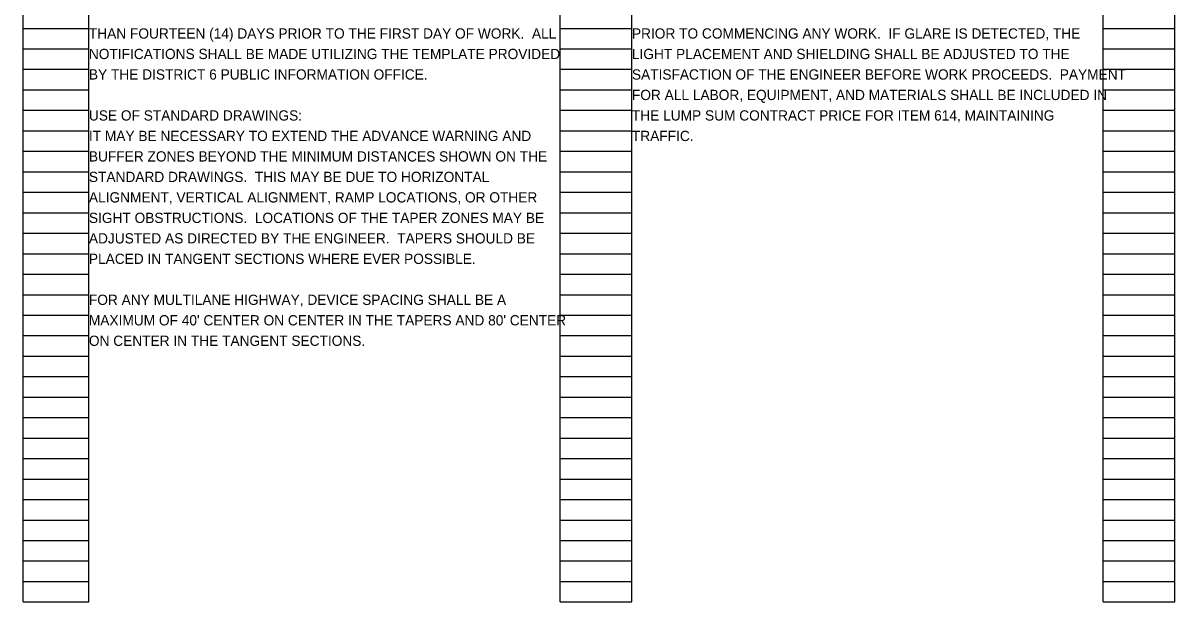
# Model space of a CAD drawing. Extents: x 0 to 32, y -44 to 21.1.
# Drawn here: x 1.5 to 17.24, y 0.98 to 8.89 of the extents above; entities that cross this region are included whole.
import ezdxf

# ---------------------------------------------------------------- set-up
doc = ezdxf.new("R2010")
doc.units = 0
doc.layers.add('SH_Data', color=7, linetype='Continuous')
doc.layers.add('SH_Text', color=7, linetype='Continuous')

msp = doc.modelspace()

# ---------------------------------------------------------------- linework, layer by layer
at = {"layer": 'SH_Data'}
for p, q in [((1.5, 0.98), (1.5, 21.14)), ((2.4, 0.98), (2.4, 21.14)), ((8.84, 0.98), (8.84, 21.14)), ((9.82, 0.98), (9.82, 21.14)), ((16.26, 0.98), (16.26, 21.14)), ((17.24, 0.98), (17.24, 21.14)), ((1.5, 8.82), (2.4, 8.82)), ((8.84, 8.82), (9.82, 8.82)), ((16.26, 8.82), (17.24, 8.82)), ((1.5, 8.54), (2.4, 8.54)), ((8.84, 8.54), (9.82, 8.54)), ((16.26, 8.54), (17.24, 8.54)), ((1.5, 8.26), (2.4, 8.26)), ((8.84, 8.26), (9.82, 8.26)), ((16.26, 8.26), (17.24, 8.26)), ((1.5, 7.98), (2.4, 7.98)), ((8.84, 7.98), (9.82, 7.98)), ((16.26, 7.98), (17.24, 7.98)), ((1.5, 7.7), (2.4, 7.7)), ((8.84, 7.7), (9.82, 7.7)), ((16.26, 7.7), (17.24, 7.7)), ((1.5, 7.42), (2.4, 7.42)), ((8.84, 7.42), (9.82, 7.42)), ((16.26, 7.42), (17.24, 7.42)), ((1.5, 7.14), (2.4, 7.14)), ((8.84, 7.14), (9.82, 7.14)), ((16.26, 7.14), (17.24, 7.14)), ((1.5, 6.86), (2.4, 6.86)), ((8.84, 6.86), (9.82, 6.86)), ((16.26, 6.86), (17.24, 6.86)), ((1.5, 6.58), (2.4, 6.58)), ((8.84, 6.58), (9.82, 6.58)), ((16.26, 6.58), (17.24, 6.58)), ((1.5, 6.3), (2.4, 6.3)), ((8.84, 6.3), (9.82, 6.3)), ((16.26, 6.3), (17.24, 6.3)), ((1.5, 6.02), (2.4, 6.02)), ((8.84, 6.02), (9.82, 6.02)), ((16.26, 6.02), (17.24, 6.02)), ((1.5, 5.74), (2.4, 5.74)), ((8.84, 5.74), (9.82, 5.74)), ((16.26, 5.74), (17.24, 5.74)), ((1.5, 5.46), (2.4, 5.46)), ((8.84, 5.46), (9.82, 5.46)), ((16.26, 5.46), (17.24, 5.46)), ((1.5, 5.18), (2.4, 5.18)), ((8.84, 5.18), (9.82, 5.18)), ((16.26, 5.18), (17.24, 5.18)), ((1.5, 4.9), (2.4, 4.9)), ((8.84, 4.9), (9.82, 4.9)), ((16.26, 4.9), (17.24, 4.9)), ((1.5, 4.62), (2.4, 4.62)), ((8.84, 4.62), (9.82, 4.62)), ((16.26, 4.62), (17.24, 4.62)), ((1.5, 4.34), (2.4, 4.34)), ((8.84, 4.34), (9.82, 4.34)), ((16.26, 4.34), (17.24, 4.34)), ((1.5, 4.06), (2.4, 4.06)), ((8.84, 4.06), (9.82, 4.06)), ((16.26, 4.06), (17.24, 4.06)), ((1.5, 3.78), (2.4, 3.78)), ((8.84, 3.78), (9.82, 3.78)), ((16.26, 3.78), (17.24, 3.78)), ((1.5, 3.5), (2.4, 3.5)), ((8.84, 3.5), (9.82, 3.5)), ((16.26, 3.5), (17.24, 3.5)), ((1.5, 3.22), (2.4, 3.22)), ((8.84, 3.22), (9.82, 3.22)), ((16.26, 3.22), (17.24, 3.22)), ((1.5, 2.94), (2.4, 2.94)), ((8.84, 2.94), (9.82, 2.94)), ((16.26, 2.94), (17.24, 2.94)), ((1.5, 2.66), (2.4, 2.66)), ((8.84, 2.66), (9.82, 2.66)), ((16.26, 2.66), (17.24, 2.66)), ((1.5, 2.38), (2.4, 2.38)), ((8.84, 2.38), (9.82, 2.38)), ((16.26, 2.38), (17.24, 2.38)), ((1.5, 2.1), (2.4, 2.1)), ((8.84, 2.1), (9.82, 2.1)), ((16.26, 2.1), (17.24, 2.1)), ((1.5, 1.82), (2.4, 1.82)), ((8.84, 1.82), (9.82, 1.82)), ((16.26, 1.82), (17.24, 1.82)), ((1.5, 1.54), (2.4, 1.54)), ((8.84, 1.54), (9.82, 1.54)), ((16.26, 1.54), (17.24, 1.54)), ((1.5, 1.26), (2.4, 1.26)), ((8.84, 1.26), (9.82, 1.26)), ((16.26, 1.26), (17.24, 1.26)), ((1.5, 0.98), (2.4, 0.98)), ((8.84, 0.98), (9.82, 0.98)), ((16.26, 0.98), (17.24, 0.98))]:
    msp.add_line(p, q, dxfattribs=at)

# ---------------------------------------------------------------- texts
at = {"layer": 'SH_Text'}
for s, p in [('THAN FOURTEEN (14) DAYS PRIOR TO THE FIRST DAY OF WORK.  ALL ', (2.4, 8.68)), ('PRIOR TO COMMENCING ANY WORK.  IF GLARE IS DETECTED, THE ', (9.82, 8.68)), ('NOTIFICATIONS SHALL BE MADE UTILIZING THE TEMPLATE PROVIDED ', (2.4, 8.4)), ('LIGHT PLACEMENT AND SHIELDING SHALL BE ADJUSTED TO THE ', (9.82, 8.4)), ('BY THE DISTRICT 6 PUBLIC INFORMATION OFFICE.', (2.4, 8.12)), ('SATISFACTION OF THE ENGINEER BEFORE WORK PROCEEDS.  PAYMENT ', (9.82, 8.12)), ('FOR ALL LABOR, EQUIPMENT, AND MATERIALS SHALL BE INCLUDED IN ', (9.82, 7.84)), ('USE OF STANDARD DRAWINGS:', (2.4, 7.56)), ('THE LUMP SUM CONTRACT PRICE FOR ITEM 614, MAINTAINING ', (9.82, 7.56)), ('IT MAY BE NECESSARY TO EXTEND THE ADVANCE WARNING AND ', (2.4, 7.28)), ('TRAFFIC.', (9.82, 7.28)), ('BUFFER ZONES BEYOND THE MINIMUM DISTANCES SHOWN ON THE ', (2.4, 7)), ('STANDARD DRAWINGS.  THIS MAY BE DUE TO HORIZONTAL ', (2.4, 6.72)), ('ALIGNMENT, VERTICAL ALIGNMENT, RAMP LOCATIONS, OR OTHER ', (2.4, 6.44)), ('SIGHT OBSTRUCTIONS.  LOCATIONS OF THE TAPER ZONES MAY BE ', (2.4, 6.16)), ('ADJUSTED AS DIRECTED BY THE ENGINEER.  TAPERS SHOULD BE ', (2.4, 5.88)), ('PLACED IN TANGENT SECTIONS WHERE EVER POSSIBLE.  ', (2.4, 5.6)), ('FOR ANY MULTILANE HIGHWAY, DEVICE SPACING SHALL BE A ', (2.4, 5.04)), ("MAXIMUM OF 40' CENTER ON CENTER IN THE TAPERS AND 80' CENTER ", (2.4, 4.76)), ('ON CENTER IN THE TANGENT SECTIONS.', (2.4, 4.48))]:
    msp.add_text(s, height=0.14, dxfattribs=at).set_placement(p)

doc.saveas('drawing.dxf')
